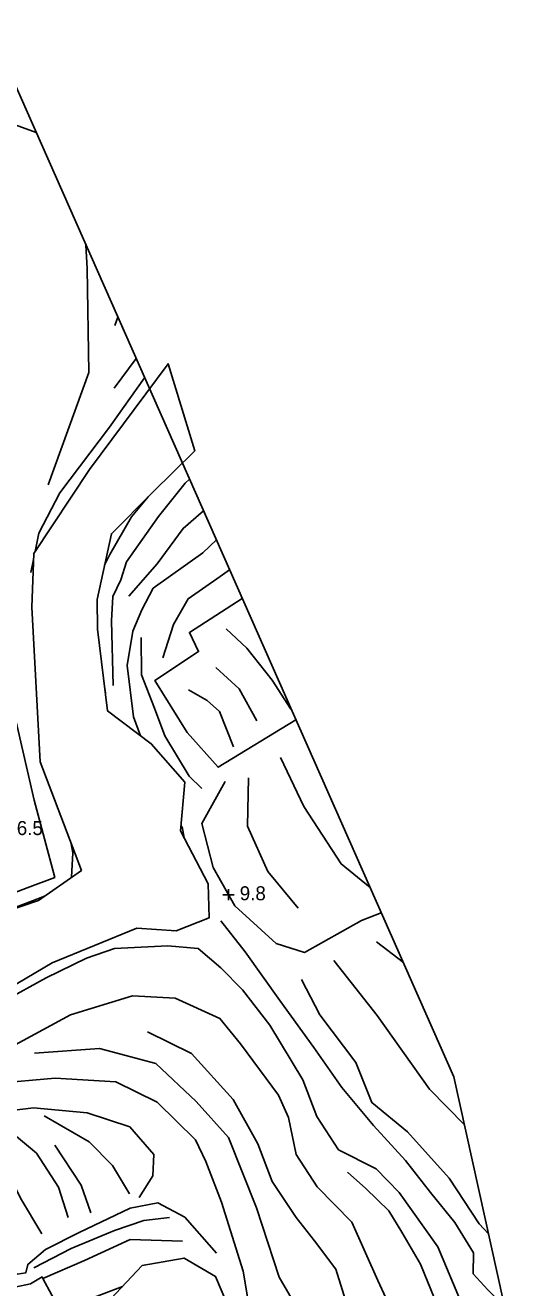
# Model space of a CAD drawing. Extents: x 2316231 to 2323598, y 363169 to 371906.
# Drawn here: x 2320838.7 to 2321018, y 364866.8 to 365317.1 of the extents above; entities that cross this region are included whole.
import ezdxf

# ---------------------------------------------------------------- set-up
doc = ezdxf.new("R2010")
doc.units = 0
for name, color, linetype in [('RD_DTM_BkLn1', 7, 'Continuous'), ('RD_DTM_Holes', 7, 'Continuous'), ('RD_DTM_TinHull', 7, 'Continuous'), ('RD_DTM_Void', 7, 'Continuous'), ('RD_EX_Road', 7, 'Continuous')]:
    doc.layers.add(name, color=color, linetype=linetype)

msp = doc.modelspace()

# ---------------------------------------------------------------- linework, layer by layer
at = {"layer": 'RD_DTM_BkLn1'}
for p, q in [((2320870.718, 365210.015), (2320871.726, 365213.025)), ((2320870.441, 365187.718), (2320878.24, 365198.311)), ((2320861.375, 365193.255), (2320846.944, 365153.16)), ((2320902.08, 365128.952), (2320906.91, 365133.559)), ((2320884.308, 365116.322), (2320902.08, 365128.952)), ((2320841.672, 365126.61), (2320840.755, 365121.979)), ((2320908.271, 365120.509), (2320911.627, 365122.905)), ((2320866.26, 365121.105), (2320866.26, 365121.105)), ((2320864.35, 365112.225), (2320864.364, 365112.374)), ((2320918.026, 365031.409), (2320918.356, 365048.753)), ((2320891.521, 364994.077), (2320891.702, 364994.218)), ((2320964.036, 364990.242), (2320973.64, 364982.841)), ((2320876.17, 364884.08), (2320894.783, 364883.408))]:
    msp.add_line(p, q, dxfattribs=at)
for points in [[(2320860.368, 365238.678), (2320860.772, 365230.37), (2320861.375, 365193.255)], [(2320881.314, 365191.369), (2320868.803, 365173.805), (2320851.011, 365150.415), (2320843.516, 365135.925), (2320842.23, 365129.429)], [(2320872.806, 365119.359), (2320874.789, 365125.763), (2320886.252, 365141.918), (2320895.724, 365153.819), (2320897.325, 365155.206)], [(2320867.019, 365124.601), (2320868.889, 365128.342), (2320876.643, 365141.765), (2320882.608, 365148.902)], [(2320902.319, 365143.927), (2320895.039, 365137.672), (2320885.735, 365125.001), (2320875.701, 365113.473)], [(2320872.806, 365119.359), (2320869.927, 365113.427), (2320869.517, 365104.741), (2320870.074, 365081.68)], [(2320887.838, 365091.464), (2320891.644, 365103.419), (2320896.824, 365112.567), (2320908.271, 365120.509)], [(2320884.308, 365116.322), (2320880.342, 365108.621), (2320877.14, 365101.05), (2320875.054, 365088.723), (2320877.342, 365070.517), (2320879.837, 365063.746)], [(2320910.444, 365101.816), (2320917.826, 365094.914), (2320926.853, 365083.544), (2320933.514, 365073.176)], [(2320901.673, 365044.893), (2320897.181, 365049.286), (2320888.487, 365063.651), (2320884.879, 365073.566), (2320880.182, 365085.44), (2320880.116, 365098.705)], [(2320906.753, 365088.109), (2320915.041, 365080.466), (2320921.411, 365068.995)], [(2320867.323, 365078.871), (2320867.26, 365079.878), (2320867.151, 365080.234)], [(2320897.008, 365080.14), (2320903.663, 365076.262), (2320908.031, 365072.312), (2320913.039, 365059.779)], [(2320929.792, 365055.945), (2320938.093, 365038.538), (2320951.443, 365018.028), (2320961.81, 365009.56)], [(2320895.429, 365027.351), (2320894.767, 365031.189), (2320894.304, 365031.536)], [(2320918.026, 365031.409), (2320925.299, 365015.269), (2320936.133, 365002.168)], [(2320855.146, 365025.128), (2320855.746, 365021.963), (2320855.254, 365013.314), (2320855.175, 365013.168)], [(2320845.795, 365006.576), (2320842.807, 365005.435), (2320824.622, 364998.563)], [(2320908.522, 364997.717), (2320917.208, 364986.663), (2320929.547, 364969.312), (2320941.727, 364952.475), (2320951.651, 364938.282), (2320962.989, 364924.745), (2320974.367, 364912.172), (2320983.382, 364900.815), (2320991.979, 364890.119), (2320998.704, 364879.261), (2320998.587, 364871.774), (2321003.76, 364866.025), (2321009.84, 364859.987)], [(2320789.301, 364937.875), (2320795.11, 364943.095), (2320806.689, 364952.583), (2320818.553, 364960.506), (2320831.082, 364969.075), (2320846.132, 364977.365), (2320860.519, 364984.44), (2320870.598, 364987.867), (2320889.653, 364988.831), (2320900.365, 364987.807), (2320908.475, 364980.988), (2320916.282, 364973.127), (2320926.017, 364960.544), (2320937.809, 364940.963), (2320942.748, 364927.859), (2320950.518, 364916.033), (2320963.998, 364909.262), (2320972.13, 364900.847), (2320985.96, 364881.366), (2320994.687, 364860.701), (2321000.435, 364842.191), (2321006.362, 364819.106), (2321003.87, 364792.554)], [(2320948.784, 364983.503), (2320964.327, 364963.911), (2320982.981, 364937.662), (2320995.492, 364924.909)], [(2320937.307, 364976.716), (2320943.814, 364964.124), (2320956.707, 364947.169), (2320962.39, 364932.887), (2320975.088, 364922.484), (2320989.962, 364905.868), (2321000.676, 364889.661), (2321004.082, 364886.043)], [(2320810.535, 364940.389), (2320825.111, 364948.104), (2320854.856, 364964.167), (2320876.979, 364971.002), (2320892.242, 364970.12), (2320908.18, 364962.846), (2320915.576, 364953.824), (2320929.031, 364935.515), (2320932.634, 364927.541), (2320935.334, 364914.389), (2320942.929, 364902.839), (2320955.2, 364890.276), (2320964.566, 364869.376), (2320974.238, 364848.22), (2320976.597, 364827.739), (2320975.536, 364803.965), (2320965.865, 364783.98)], [(2320941.949, 364883.529), (2320935.363, 364891.86), (2320926.824, 364904.71), (2320921.676, 364918.186), (2320912.92, 364933.945), (2320898.007, 364950.36), (2320882.35, 364958.082)], [(2320842.068, 364950.483), (2320865.195, 364952.17), (2320885.293, 364946.76), (2320899.752, 364933.281), (2320911.245, 364920.421), (2320921.248, 364895.307), (2320929.317, 364870.652), (2320939.891, 364852.388), (2320945.723, 364827.042)], [(2320810.699, 364934.838), (2320827.79, 364939.679), (2320849.336, 364941.617), (2320871.046, 364940.278), (2320885.78, 364932.975), (2320899.408, 364919.593), (2320903.204, 364911.842), (2320908.706, 364897.372), (2320916.477, 364872.722), (2320919.668, 364853.585), (2320919.271, 364821.299), (2320922.598, 364793.419), (2320920.431, 364778.915), (2320915.816, 364782.273), (2320909.315, 364786.101), (2320902.858, 364790.501), (2320893.539, 364802.97), (2320886.757, 364818.567), (2320882.826, 364824.202)], [(2320812.484, 364926.368), (2320825.087, 364929.005), (2320841.597, 364930.986), (2320860.776, 364929.21), (2320875.998, 364924.174), (2320884.561, 364914.383), (2320884.215, 364906.697), (2320879.405, 364899.068)], [(2320829.854, 364925.49), (2320842.737, 364914.774), (2320850.563, 364902.709), (2320853.989, 364891.868)], [(2320875.923, 364900.265), (2320869.854, 364910.457), (2320861.579, 364918.862), (2320845.459, 364928.175)], [(2320793.873, 364921.848), (2320799.854, 364913.658), (2320810.261, 364899.957), (2320823.907, 364883.193), (2320829.173, 364876.502), (2320835.837, 364871.647), (2320838.869, 364872.123), (2320839.583, 364875.172), (2320845.917, 364880.468), (2320857.895, 364886.508), (2320876.165, 364895.225), (2320885.982, 364897.084), (2320895.618, 364891.956), (2320906.91, 364879.194)], [(2320822.703, 364921.993), (2320831.286, 364910.416), (2320837.023, 364898.824), (2320844.647, 364886.096)], [(2320862.136, 364893.515), (2320858.694, 364903.38), (2320849.26, 364917.637)], [(2320988.788, 364790.183), (2320992.4, 364809.56), (2320991.664, 364832.54), (2320987.459, 364856.087), (2320984.732, 364862.94), (2320979.791, 364875.211), (2320973.159, 364886.674), (2320968.431, 364894.237), (2320960.28, 364902.211), (2320953.763, 364908.088)], [(2320841.815, 364873.959), (2320855.055, 364880.825), (2320870.564, 364887.299), (2320881.038, 364890.791), (2320890.235, 364891.862)], [(2320941.949, 364883.529), (2320949.496, 364873.493), (2320957.099, 364849.476), (2320961.964, 364833.885), (2320963.6, 364805.937), (2320958.573, 364784.428), (2320953.495, 364777.255), (2320946.856, 364770.739), (2320940.697, 364765.929), (2320936.198, 364762.314)]]:
    msp.add_lwpolyline(points, dxfattribs=at)
at = {"layer": 'RD_DTM_Holes'}
for points in [[(2320789.36, 364986.622), (2320843.478, 365004.948), (2320858.744, 365015.676), (2320844.012, 365054.379), (2320841.052, 365109.615), (2320841.748, 365128.702), (2320861.62, 365158.685), (2320889.694, 365196.425), (2320899.199, 365165.298), (2320884.172, 365150.464), (2320869.442, 365135.757), (2320864.349, 365112.305)], [(2320864.349, 365112.305), (2320864.446, 365101.76), (2320868.111, 365072.602), (2320883.68, 365060.844), (2320895.695, 365047.166), (2320894.151, 365029.817), (2320903.976, 365010.862), (2320904.335, 364998.759), (2320892.606, 364994.155), (2320878.582, 364995.124), (2320848.371, 364982.736), (2320811.415, 364960.904)], [(2320860.417, 364847.473), (2320867.353, 364860.808), (2320880.49, 364874.76), (2320895.367, 364877.398), (2320906.613, 364870.852), (2320913.685, 364854.024), (2320905.951, 364833.819), (2320891.544, 364824.673), (2320880.937, 364824.1), (2320869.171, 364833.142), (2320860.417, 364847.473)]]:
    msp.add_lwpolyline(points, dxfattribs=at)
at = {"layer": 'RD_DTM_TinHull'}
msp.add_lwpolyline([(2320809.363, 365353.877), (2320991.706, 364942.038), (2321080.196, 364541.654), (2321314.653, 364017.924), (2320828.919, 363723.372), (2320765.1, 363867.546), (2320638.089, 364094.01), (2320532.322, 364258.493), (2320402.792, 364459.125), (2320263.728, 364603.235), (2320177.718, 364755.167), (2319998.644, 364909.111), (2319975.332, 365147.552), (2319890.016, 365354.444)], dxfattribs=at)
at = {"layer": 'RD_DTM_Void'}
for p, q in [((2320909.256, 365007.026), (2320913.256, 365007.026)), ((2320911.256, 365005.026), (2320911.256, 365009.026))]:
    msp.add_line(p, q, dxfattribs=at)
at = {"layer": 'RD_EX_Road'}
msp.add_line((2320845.019, 364870.149), (2320851.364, 364858.212), dxfattribs=at)
for points in [[(2320842.562, 365278.895), (2320829.9, 365283.568), (2320790.99, 365300.206), (2320749.339, 365316.878), (2320742.072, 365315.975), (2320737.331, 365311.106)], [(2320916.166, 365112.652), (2320897.279, 365100.569), (2320900.59, 365093.766), (2320884.986, 365083.46), (2320896.449, 365064.908), (2320907.531, 365052.458), (2320935.331, 365069.367)], [(2320654.535, 365098.797), (2320691.565, 365061.331), (2320718.294, 365036.003), (2320741.317, 365013.497), (2320764.632, 364992.176), (2320772.607, 364984.419), (2320807.765, 364997.885), (2320830.062, 365005.932), (2320839.345, 365009.442), (2320849.262, 365013.157), (2320841.906, 365040.778), (2320835.424, 365068.73), (2320835.006, 365073.988), (2320834.305, 365089.347), (2320834.753, 365097.413), (2320834.709, 365104.321)], [(2320965.776, 365000.602), (2320958.653, 364997.828), (2320938.4, 364986.451), (2320928.245, 364989.658), (2320913.546, 365002.997), (2320905.723, 365016.765), (2320901.776, 365032.413), (2320910.082, 365047.358)], [(2320845.019, 364870.149), (2320859.906, 364876.498), (2320876.17, 364884.08)], [(2320828.446, 364866.907), (2320834.968, 364867.076), (2320840.582, 364868.203), (2320844.74, 364870.674), (2320845.019, 364870.149)], [(2320851.364, 364858.212), (2320859.321, 364861.945), (2320873.393, 364867.223)]]:
    msp.add_lwpolyline(points, dxfattribs=at)

# ---------------------------------------------------------------- texts
at = {"layer": 'RD_DTM_Void'}
for s, p in [('6.5', (2320835.689, 365028.292)), ('9.8', (2320915.256, 365005.026))]:
    msp.add_text(s, height=5, dxfattribs=at).set_placement(p)

doc.saveas('drawing.dxf')
